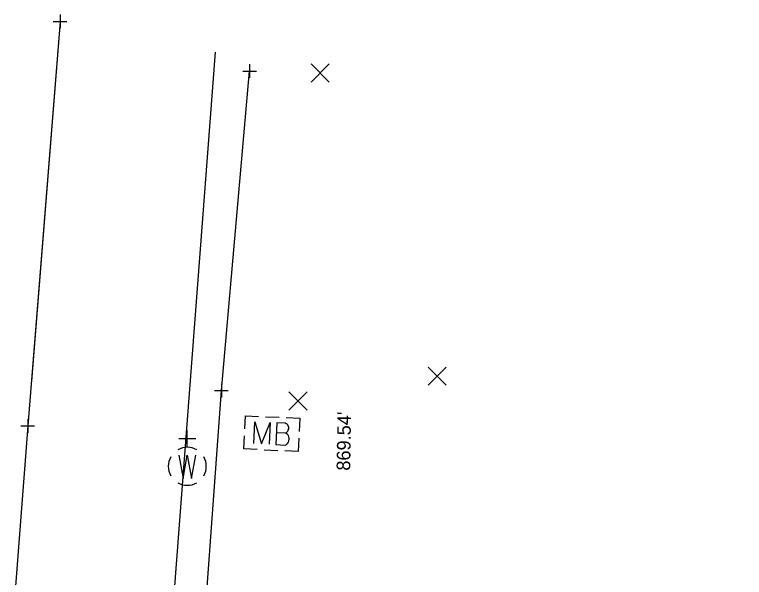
# Model space of a CAD drawing. Extents: x 1380440 to 1381945, y 468756 to 470369.
# Drawn here: x 1381624.1 to 1381677.8, y 470283.3 to 470324.7 of the extents above; entities that cross this region are included whole.
import ezdxf

# ---------------------------------------------------------------- set-up
doc = ezdxf.new("R2010")
doc.units = 0
for name, color, linetype in [('GE_P_Driveway_CL', 7, 'Continuous'), ('PM_X_CL_Double_Solid', 7, 'Continuous'), ('RD_P_Cells', 7, 'Continuous'), ('RW_P_Const_Limits', 7, 'Continuous'), ('RW_P_Esmt_TMP', 7, 'Continuous'), ('SC_Scratch1', 7, 'Continuous'), ('SC_Shading1', 7, 'Continuous'), ('SH_Named_Boundary', 7, 'Continuous'), ('UT_X_Water', 7, 'Continuous')]:
    doc.layers.add(name, color=color, linetype=linetype)

msp = doc.modelspace()

# ---------------------------------------------------------------- linework, layer by layer
at = {"layer": 'GE_P_Driveway_CL'}
for p, q in [((1381645.907, 470319.767), (1381647.241, 470321.102)), ((1381645.907, 470321.102), (1381647.241, 470319.767)), ((1381654.522, 470297.423), (1381655.856, 470298.758)), ((1381654.522, 470298.758), (1381655.856, 470297.423)), ((1381644.263, 470295.596), (1381645.597, 470296.931)), ((1381644.263, 470296.931), (1381645.597, 470295.596))]:
    msp.add_line(p, q, dxfattribs=at)
at = {"layer": 'PM_X_CL_Double_Solid'}
msp.add_line((1381627.408, 470324.235), (1381625.289, 470297.732), dxfattribs=at)
at = {"layer": 'RD_P_Cells'}
for p, q in [((1381642.551, 470295.108), (1381643.552, 470295.062)), ((1381643.006, 470293.864), (1381643.006, 470293.864)), ((1381642.439, 470292.667), (1381643.439, 470292.621))]:
    msp.add_line(p, q, dxfattribs=at)
for points in [[(1381641.02, 470294.208), (1381641.064, 470295.177), (1381642.033, 470295.132)], [(1381644.068, 470295.038), (1381645.06, 470294.992), (1381645.015, 470294.023)], [(1381641.674, 470293.125), (1381641.748, 470294.723), (1381642.253, 470293.098), (1381642.88, 470294.671), (1381642.807, 470293.073)], [(1381644.03, 470293.886), (1381644.096, 470293.946), (1381644.135, 470293.982), (1381644.162, 470294.019), (1381644.176, 470294.043), (1381644.203, 470294.093), (1381644.218, 470294.13), (1381644.247, 470294.217), (1381644.249, 470294.255), (1381644.251, 470294.305), (1381644.242, 470294.381), (1381644.219, 470294.445), (1381644.184, 470294.497), (1381644.123, 470294.55), (1381644.074, 470294.578), (1381644.05, 470294.592), (1381643.988, 470294.62), (1381643.371, 470294.648), (1381643.298, 470293.05), (1381643.99, 470293.018), (1381644.08, 470293.064), (1381644.159, 470293.124), (1381644.226, 470293.222), (1381644.269, 470293.333), (1381644.287, 470293.446), (1381644.29, 470293.521), (1381644.269, 470293.598), (1381644.224, 470293.713), (1381644.164, 470293.792), (1381644.03, 470293.886), (1381643.338, 470293.918)], [(1381641.921, 470292.691), (1381640.952, 470292.736), (1381640.997, 470293.705)], [(1381644.992, 470293.521), (1381644.948, 470292.552), (1381643.955, 470292.597)]]:
    msp.add_lwpolyline(points, dxfattribs=at)
at = {"layer": 'RW_P_Const_Limits'}
for p, q in [((1381636.779, 470292.849), (1381636.779, 470294.121)), ((1381637.414, 470293.486), (1381636.142, 470293.486)), ((1381636.779, 470291.449), (1381636.779, 470291.449))]:
    msp.add_line(p, q, dxfattribs=at)
msp.add_lwpolyline([(1381636.142, 470292.269), (1381636.461, 470290.546), (1381636.779, 470292.269), (1381637.099, 470290.546), (1381637.416, 470292.269)], dxfattribs=at)
for start, end in [(60.0184, 120.0157), (150.0184, 209.9816), (330.0184, 29.9816), (239.9843, 299.9816)]:
    msp.add_arc((1381636.779, 470291.451), 1.4, start, end, dxfattribs=at)
at = {"layer": 'RW_P_Esmt_TMP'}
msp.add_lwpolyline([(1381677.821, 470243.959), (1381667.493, 470244.246), (1381661.321, 470244.629), (1381647.841, 470248.496), (1381643.906, 470251.149), (1381641.086, 470253.807), (1381638.634, 470258.076), (1381637.552, 470273.11), (1381639.286, 470297.033), (1381641.369, 470320.574)], dxfattribs=at)
at = {"layer": 'SC_Shading1'}
msp.add_lwpolyline([(1381627.408, 470324.235), (1381625.025, 470294.425), (1381622.344, 470259.947), (1381618.765, 470220.138), (1381616.919, 470200.188), (1381615.103, 470178.831), (1381610.946, 470124.776), (1381606.492, 470071.232), (1381602.26, 470019.361), (1381598.177, 469969.796), (1381595.011, 469928.064), (1381590.91, 469878.811), (1381589.36, 469859.114), (1381585.986, 469815.579)], dxfattribs=at)
at = {"layer": 'SH_Named_Boundary'}
for p, q in [((1381627.408, 470324.735), (1381627.408, 470323.735)), ((1381626.908, 470324.235), (1381627.908, 470324.235)), ((1381627.408, 470324.235), (1381627.408, 470324.235)), ((1381641.369, 470321.074), (1381641.369, 470320.074)), ((1381640.869, 470320.574), (1381641.869, 470320.574)), ((1381641.369, 470320.574), (1381641.369, 470320.574)), ((1381639.286, 470297.533), (1381639.286, 470296.533)), ((1381638.786, 470297.033), (1381639.786, 470297.033)), ((1381639.286, 470297.033), (1381639.286, 470297.033)), ((1381625.025, 470294.925), (1381625.025, 470293.925)), ((1381624.525, 470294.425), (1381625.525, 470294.425)), ((1381625.025, 470294.425), (1381625.025, 470294.425))]:
    msp.add_line(p, q, dxfattribs=at)
at = {"layer": 'UT_X_Water'}
msp.add_line((1381630.263, 470209.692), (1381638.864, 470321.963), dxfattribs=at)

# ---------------------------------------------------------------- texts
at = {"layer": 'SC_Scratch1'}
msp.add_text("869.54'", height=1, rotation=89.082, dxfattribs=at).set_placement((1381648.775, 470291.126))

doc.saveas('drawing.dxf')
